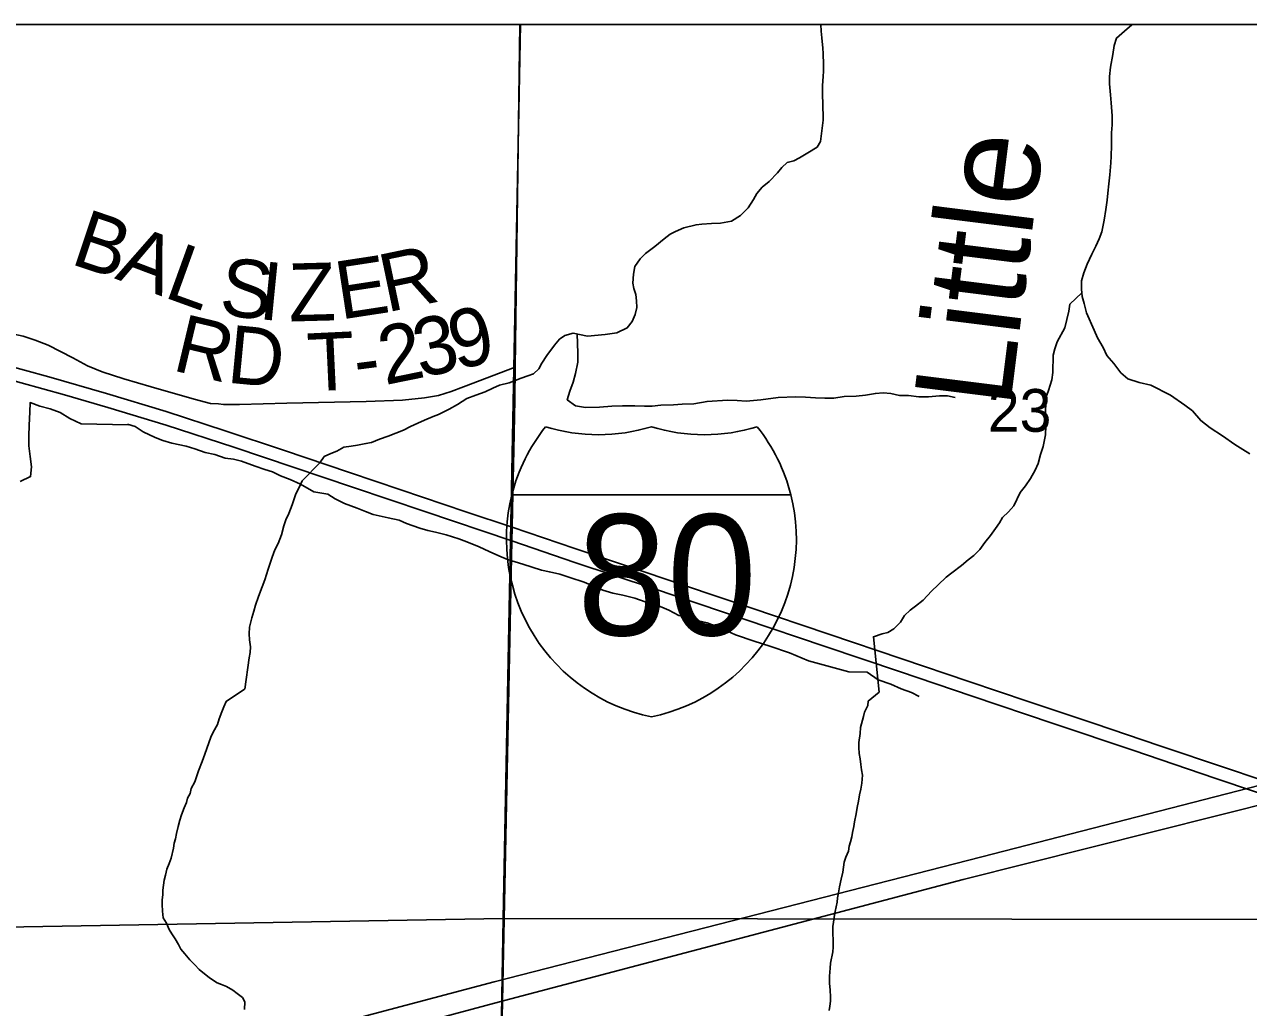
# Model space of a CAD drawing. Extents: x -8.5 to 18.7, y -20.3 to 7.
# Drawn here: x 6.749 to 9.147, y 5.013 to 6.938 of the extents above; entities that cross this region are included whole.
import ezdxf

# ---------------------------------------------------------------- set-up
doc = ezdxf.new("R2010")
doc.units = 0
for name, color, linetype in [('Default', 7, 'Continuous'), ('GM_X_Corporation', 7, 'Continuous'), ('GM_X_Interstate_Location', 7, 'Continuous'), ('GM_X_Interstate_Route', 7, 'Continuous'), ('GM_X_Interstate_Shield', 7, 'Continuous'), ('GM_X_Minor_River', 7, 'Continuous'), ('GM_X_Minor_River_Text', 7, 'Continuous'), ('GM_X_Rail_Line', 7, 'Continuous'), ('GM_X_Section', 7, 'Continuous'), ('GM_X_Section_Text', 7, 'Continuous'), ('GM_X_Township_Road', 7, 'Continuous'), ('GM_X_Township_Road_Text', 7, 'Continuous'), ('SH_Cut_Line', 7, 'Continuous')]:
    doc.layers.add(name, color=color, linetype=linetype)

msp = doc.modelspace()

# ---------------------------------------------------------------- linework, layer by layer
at = {"layer": 'Default'}
for points in [[(7.7208, 6.938), (5.7052, 6.938), (5.695, 5.1526), (7.6869, 5.1871)], [(9.7054, 6.938), (7.7208, 6.938), (7.6869, 5.1871), (9.6798, 5.1845)]]:
    msp.add_lwpolyline(points, close=True, dxfattribs=at)
at = {"layer": 'GM_X_Corporation'}
msp.add_lwpolyline([(3.6318, 1.1236), (5.043, 1.1473), (5.1251, 1.1484), (7.5383, 1.181), (7.59, 1.1818), (9.5569, 1.2131), (11.5871, 1.2389), (11.6132, 2.2462), (11.64, 3.2551), (11.6653, 4.2586), (11.6686, 4.5917), (11.6689, 4.6186), (11.6732, 5.0475), (11.7049, 6.938), (-0.1911, 6.938)], dxfattribs=at)
at = {"layer": 'GM_X_Interstate_Route'}
for points in [[(6.7004, 6.2739), (6.7966, 6.2478), (6.9096, 6.2154), (7.0268, 6.18), (7.1419, 6.1424), (7.2562, 6.1042), (7.3856, 6.0606), (7.4865, 6.0267), (7.6137, 5.9836), (7.7046, 5.9532), (7.8274, 5.9118), (7.9288, 5.8777), (8.0421, 5.839), (8.1703, 5.7961), (8.3249, 5.7439), (8.4679, 5.6957), (8.5992, 5.6514), (8.7155, 5.6122), (8.8446, 5.5689), (8.9735, 5.5253), (9.1021, 5.4821), (9.2338, 5.4376)], [(6.6997, 6.2477), (6.8274, 6.2128), (6.9123, 6.1881), (7.0264, 6.1533), (7.159, 6.1101), (7.3936, 6.0312), (7.5332, 5.9844), (7.7039, 5.9264), (7.8274, 5.8845), (7.9816, 5.8332), (8.1593, 5.7732), (8.3179, 5.7196), (8.4633, 5.6707), (8.6059, 5.6226), (8.7648, 5.5691), (8.9225, 5.5158), (9.0814, 5.4621), (9.2385, 5.4092)]]:
    msp.add_lwpolyline(points, dxfattribs=at)
at = {"layer": 'GM_X_Interstate_Shield'}
for p, q in [((7.704, 6.0169), (8.2505, 6.0169)), ((8.2505, 6.0169), (7.704, 6.0169)), ((8.2505, 6.0169), (7.704, 6.0169))]:
    msp.add_line(p, q, dxfattribs=at)
for centre, start, end in [((8.0483, 5.9299), 141.669, 165.8066), ((7.8735, 6.4897), 253.0091, 286.9909), ((8.081, 6.4897), 253.0091, 286.9909), ((7.9062, 5.9299), 14.1934, 38.331), ((8.0483, 5.9299), 165.8066, 258.463), ((7.9062, 5.9299), 281.537, 14.1934)]:
    msp.add_arc(centre, 0.3551, start, end, dxfattribs=at)
at = {"layer": 'GM_X_Minor_River'}
for points in [[(8.309, 6.938), (8.309, 6.938), (8.3098, 6.9251), (8.3114, 6.9121), (8.313, 6.8916), (8.3138, 6.881), (8.3147, 6.8597), (8.3147, 6.8468), (8.314, 6.8362), (8.3126, 6.8187), (8.3127, 6.7975), (8.3135, 6.7853), (8.3137, 6.7504), (8.3108, 6.7245), (8.3086, 6.7086), (8.3018, 6.6979), (8.2837, 6.6864), (8.2678, 6.6765), (8.2564, 6.6711), (8.2435, 6.668), (8.233, 6.6581), (8.2247, 6.6475), (8.208, 6.6307), (8.1944, 6.6192), (8.1839, 6.607), (8.1771, 6.5949), (8.1666, 6.5789), (8.1522, 6.5636), (8.134, 6.5529), (8.1128, 6.549), (8.0953, 6.5482), (8.0764, 6.5466), (8.065, 6.5458), (8.0407, 6.5396), (8.0248, 6.5327), (8.0142, 6.5274), (8.0021, 6.5182), (7.984, 6.5029), (7.9658, 6.4892), (7.9553, 6.4793), (7.9447, 6.464), (7.9425, 6.4488), (7.9411, 6.4314), (7.9426, 6.4207), (7.9465, 6.4094), (7.9481, 6.3965), (7.9489, 6.3835), (7.9452, 6.3699), (7.9399, 6.3562), (7.9301, 6.344), (7.9097, 6.334), (7.8869, 6.3309), (7.852, 6.3277), (7.8239, 6.3337), (7.808, 6.3291), (7.7974, 6.3214), (7.7876, 6.31), (7.7725, 6.2894), (7.7627, 6.2749), (7.7567, 6.2635), (7.7461, 6.2536), (7.7355, 6.2498), (7.7219, 6.2452), (7.6984, 6.236), (7.6794, 6.2313), (7.6666, 6.226), (7.6514, 6.2183), (7.6332, 6.2121), (7.6158, 6.2052), (7.5976, 6.1938), (7.581, 6.1846), (7.5605, 6.1739), (7.5499, 6.17), (7.5325, 6.1631), (7.5196, 6.157), (7.5052, 6.1509), (7.4916, 6.1432), (7.4764, 6.1378), (7.4613, 6.1317), (7.4446, 6.1256), (7.4287, 6.1194), (7.4181, 6.1171), (7.4014, 6.114), (7.3893, 6.1124)], [(8.9185, 6.938), (8.9186, 6.9373), (8.9042, 6.9251), (8.8883, 6.9114), (8.8839, 6.8969), (8.8817, 6.8795), (8.8765, 6.8544), (8.8751, 6.8361), (8.8751, 6.8217), (8.8768, 6.8004)], [(8.8768, 6.8004), (8.8784, 6.7845), (8.88, 6.7594), (8.8801, 6.7412), (8.8787, 6.726), (8.8788, 6.7009), (8.8781, 6.6804), (8.8774, 6.6668), (8.8753, 6.6432), (8.8738, 6.6257), (8.8717, 6.6075), (8.8702, 6.5938), (8.868, 6.5756), (8.8643, 6.555), (8.8599, 6.5322), (8.8547, 6.5185), (8.8479, 6.5041), (8.8404, 6.4881), (8.8314, 6.4683), (8.8246, 6.4516), (8.8202, 6.4356), (8.8202, 6.4197), (8.8211, 6.4052), (8.8249, 6.3916), (8.8296, 6.3734), (8.8449, 6.3392), (8.8511, 6.3241), (8.8626, 6.3051), (8.8695, 6.29), (8.8832, 6.2741), (8.897, 6.2559), (8.9107, 6.2438), (8.9328, 6.237), (8.9556, 6.2318), (8.9944, 6.2122), (9.0226, 6.1926), (9.0378, 6.1812), (9.0538, 6.1623), (9.0721, 6.148), (9.0965, 6.1321), (9.1201, 6.1155), (9.1361, 6.1057), (9.1498, 6.0974)], [(8.8207, 6.4124), (8.7969, 6.3899), (8.7954, 6.3763), (8.7872, 6.3436), (8.7722, 6.3162), (8.7677, 6.3025), (8.7647, 6.2903), (8.7641, 6.2561), (8.7619, 6.2417), (8.7552, 6.2211), (8.7507, 6.209), (8.75, 6.1968), (8.7493, 6.1793), (8.7502, 6.1664), (8.7502, 6.152), (8.7496, 6.1345), (8.7451, 6.1117), (8.7399, 6.0957), (8.7354, 6.0783), (8.7294, 6.0653), (8.7204, 6.0486), (8.7106, 6.0341), (8.7, 6.0211), (8.6873, 5.9953), (8.6767, 5.9838), (8.6654, 5.9724), (8.6593, 5.9617), (8.6518, 5.9511), (8.642, 5.9374), (8.6307, 5.9236), (8.6209, 5.9099), (8.6088, 5.8977), (8.5982, 5.8893), (8.5846, 5.8786), (8.5657, 5.8641), (8.5551, 5.8557), (8.5393, 5.8405), (8.5264, 5.8283), (8.5098, 5.8107), (8.4947, 5.7985), (8.4841, 5.7909), (8.4735, 5.7802), (8.4652, 5.7673), (8.4524, 5.7543), (8.4403, 5.7474), (8.4297, 5.7443), (8.4122, 5.739), (8.4234, 5.63)], [(7.8318, 6.332), (7.8331, 6.2944), (7.8334, 6.2769), (7.8289, 6.2542), (7.8239, 6.2377), (7.8173, 6.2196), (7.8123, 6.203), (7.8287, 6.1912), (7.8483, 6.1876), (7.8757, 6.1883), (7.9, 6.1906), (7.9205, 6.1908), (7.9448, 6.1909), (7.9638, 6.1903), (7.979, 6.1906), (7.9958, 6.1924), (8.0208, 6.1932), (8.0376, 6.1943), (8.0604, 6.1951), (8.0863, 6.1997), (8.1266, 6.2023), (8.1456, 6.2018), (8.163, 6.2005), (8.192, 6.2027), (8.2255, 6.2071), (8.2605, 6.2084), (8.2794, 6.2078), (8.2991, 6.2065), (8.3174, 6.206), (8.3348, 6.2062), (8.3547, 6.2094), (8.3782, 6.2103), (8.3965, 6.212), (8.4163, 6.2153), (8.4316, 6.2163), (8.4467, 6.2152), (8.4633, 6.2116), (8.4808, 6.2111), (8.5012, 6.209), (8.5202, 6.2085), (8.5415, 6.2109), (8.5574, 6.2104), (8.5726, 6.2077)], [(6.7406, 6.0427), (6.7611, 6.0524), (6.7628, 6.0714), (6.7599, 6.0919), (6.7578, 6.1125), (6.7572, 6.1315), (6.7581, 6.1535), (6.7598, 6.1786), (6.7599, 6.1976), (6.7788, 6.1906), (6.7993, 6.1851), (6.819, 6.1781), (6.8378, 6.1665), (6.8598, 6.1557), (6.9522, 6.1538)], [(6.9506, 6.1549), (6.9656, 6.1507), (6.9813, 6.1404), (7.0053, 6.129), (7.0203, 6.1233), (7.0376, 6.1182), (7.0655, 6.1121), (7.0828, 6.1071), (7.1031, 6.0996), (7.122, 6.096), (7.1423, 6.0886), (7.1582, 6.0866), (7.174, 6.0824), (7.2011, 6.0732), (7.2199, 6.0666), (7.2349, 6.0616), (7.2507, 6.0543), (7.2695, 6.047), (7.2897, 6.038), (7.3159, 6.0228), (7.3431, 6.0182), (7.358, 6.0087), (7.3759, 5.9998), (7.4007, 5.9907), (7.4173, 5.9842), (7.4323, 5.9784), (7.4617, 5.9715), (7.4828, 5.9671), (7.4978, 5.9606), (7.5234, 5.9515), (7.5392, 5.9472), (7.5543, 5.9438), (7.5754, 5.9386), (7.6003, 5.9303), (7.616, 5.9245), (7.6401, 5.9147), (7.6595, 5.9058), (7.6783, 5.8976), (7.6956, 5.8903), (7.7257, 5.8811), (7.7618, 5.8694), (7.7776, 5.8659), (7.798, 5.8615), (7.8176, 5.8549), (7.8454, 5.8457), (7.8627, 5.8384), (7.8822, 5.8302), (7.9017, 5.8243), (7.9214, 5.82), (7.9448, 5.8147), (7.965, 5.8073), (7.9854, 5.8022), (8.0117, 5.7908), (8.0311, 5.7803), (8.0522, 5.7759), (8.0695, 5.7701), (8.0869, 5.7658), (8.1087, 5.7576), (8.1252, 5.7503), (8.1424, 5.7429), (8.1785, 5.7305), (8.2094, 5.7205), (8.2477, 5.7072), (8.2852, 5.6917), (8.3644, 5.6704), (8.4, 5.6694), (8.4216, 5.6543), (8.4464, 5.646), (8.4667, 5.6371), (8.487, 5.6296), (8.5019, 5.6216)], [(7.3893, 6.1124), (7.3749, 6.1101), (7.3612, 6.1024), (7.3491, 6.0978), (7.3362, 6.0917), (7.3279, 6.0795), (7.2932, 6.0444), (7.2864, 6.03), (7.2804, 6.0186), (7.2737, 5.9973), (7.267, 5.9805), (7.261, 5.9676), (7.2572, 5.9562), (7.2528, 5.9387), (7.246, 5.9212), (7.2392, 5.909), (7.234, 5.8946), (7.2265, 5.871), (7.2198, 5.8505), (7.2146, 5.8368), (7.2078, 5.8177), (7.2018, 5.801), (7.1981, 5.7888), (7.1944, 5.7759), (7.1899, 5.7577), (7.1892, 5.7447), (7.19, 5.7326), (7.1916, 5.7189), (7.1909, 5.7083), (7.1895, 5.6977), (7.1805, 5.6359)], [(7.1799, 5.6359), (7.1442, 5.6123), (7.1397, 5.6017), (7.1359, 5.5918), (7.1307, 5.5781), (7.1269, 5.5667), (7.1187, 5.5522), (7.1142, 5.5423), (7.1022, 5.5088), (7.0969, 5.4943), (7.0902, 5.4761), (7.0865, 5.4662), (7.0827, 5.4548), (7.0759, 5.4418), (7.0737, 5.4319), (7.0685, 5.4228), (7.0662, 5.4144), (7.0617, 5.4038), (7.0565, 5.3901), (7.0535, 5.3794), (7.0498, 5.3672), (7.0468, 5.3535), (7.0446, 5.3429), (7.0423, 5.3345), (7.0409, 5.3246), (7.0364, 5.3049), (7.0327, 5.295), (7.0282, 5.2836), (7.0252, 5.2721), (7.0229, 5.2623), (7.02, 5.2425), (7.0201, 5.2341), (7.0186, 5.2227), (7.0186, 5.2144), (7.0195, 5.2015), (7.021, 5.1886), (7.0272, 5.1779), (7.0325, 5.1658), (7.0379, 5.1567), (7.044, 5.1469), (7.0509, 5.1363), (7.0555, 5.1272), (7.0632, 5.1181), (7.0731, 5.106), (7.083, 5.0962), (7.0914, 5.0871), (7.1112, 5.0705), (7.1265, 5.0607), (7.1348, 5.0577), (7.1447, 5.0539), (7.1569, 5.0464), (7.166, 5.0403), (7.176, 5.032), (7.1806, 5.0237), (7.1799, 5.0085)], [(8.4234, 5.63), (8.4022, 5.613), (8.4015, 5.6039), (8.3947, 5.591), (8.3932, 5.5826), (8.3873, 5.5613), (8.3866, 5.5491), (8.3836, 5.5316), (8.3837, 5.5218), (8.3845, 5.5104), (8.3861, 5.4997), (8.3876, 5.4884), (8.3892, 5.4785), (8.3908, 5.4679), (8.3893, 5.4519), (8.3879, 5.4405), (8.3849, 5.4291), (8.3834, 5.4169), (8.3805, 5.4047), (8.3783, 5.3918), (8.3753, 5.3766), (8.3738, 5.3675), (8.3716, 5.3553), (8.3701, 5.347), (8.3671, 5.3371), (8.3649, 5.3287), (8.3634, 5.3188), (8.3582, 5.3074), (8.3552, 5.2975), (8.3537, 5.2876), (8.3523, 5.2777), (8.3493, 5.264), (8.3456, 5.2488), (8.3441, 5.2374), (8.3419, 5.2275), (8.3412, 5.2192), (8.3375, 5.2009), (8.3352, 5.1895), (8.3338, 5.1796), (8.3331, 5.1713), (8.3333, 5.131), (8.3325, 5.1219), (8.3281, 5.0998), (8.3274, 5.09), (8.326, 5.074), (8.326, 5.0603), (8.3276, 5.0466), (8.3284, 5.0337), (8.3285, 5.0254), (8.327, 5.0155), (8.3255, 5.0071)]]:
    msp.add_lwpolyline(points, dxfattribs=at)
at = {"layer": 'GM_X_Rail_Line'}
for points in [[(3.3492, 3.6263), (4.4113, 3.9753), (4.8681, 4.1485), (5.3383, 4.3406), (5.8491, 4.5056), (6.1923, 4.6193), (6.6809, 4.7548), (6.9366, 4.825), (7.6892, 5.0264), (8.5879, 5.2635), (9.4613, 5.4827), (11.0096, 5.9016), (11.7084, 6.0715), (12.7137, 6.343), (13.3579, 6.5187), (14.1524, 6.7238), (14.6912, 6.8722), (14.936, 6.938)], [(3.8129, 4.1403), (4.3242, 4.207), (4.4317, 4.2229), (4.6591, 4.2738), (5.1343, 4.3961), (5.6672, 4.5409), (6.9377, 4.8691), (7.6692, 5.0633), (8.6247, 5.3078), (9.4518, 5.5207), (10.9979, 5.9173), (11.7143, 6.0969), (12.7059, 6.3644), (13.315, 6.5285), (14.1271, 6.7413), (14.6717, 6.8937), (14.8429, 6.938)]]:
    msp.add_lwpolyline(points, dxfattribs=at)
at = {"layer": 'GM_X_Section'}
for points in [[(7.6869, 5.1871), (7.6532, 3.1997), (5.6525, 3.1789), (5.695, 5.1526)], [(9.6798, 5.1845), (9.6423, 3.2228), (7.6532, 3.1997), (7.6869, 5.1871)]]:
    msp.add_lwpolyline(points, close=True, dxfattribs=at)
at = {"layer": 'GM_X_Township_Road'}
msp.add_line((7.7104, 6.2666), (7.7196, 6.938), dxfattribs=at)
for points in [[(6.7013, 6.3356), (6.7191, 6.3335), (6.7463, 6.3274), (6.77, 6.3198), (6.7952, 6.3101), (6.8435, 6.2852), (6.8724, 6.2696), (6.9015, 6.2575), (6.9435, 6.2439), (6.9973, 6.2284), (7.0815, 6.2044), (7.1133, 6.1958), (7.1291, 6.1947)], [(7.1291, 6.1947), (7.139, 6.194), (7.1705, 6.194), (7.2632, 6.1965), (7.4182, 6.1993), (7.4897, 6.2025), (7.5329, 6.2069), (7.5603, 6.2111), (7.5853, 6.2191), (7.6094, 6.2286), (7.7104, 6.2666)], [(7.6765, 4.5738), (7.7039, 5.9264), (7.7046, 5.9532), (7.7061, 6.0185), (7.7076, 6.104), (7.7095, 6.2035), (7.7104, 6.2666)]]:
    msp.add_lwpolyline(points, dxfattribs=at)
at = {"layer": 'SH_Cut_Line'}
msp.add_lwpolyline([(18.7413, -10.9039), (18.7413, 6.938), (-8.4587, 6.938)], dxfattribs=at)

# ---------------------------------------------------------------- texts
at = {"layer": 'GM_X_Interstate_Location'}
for s in ['-', '.', ',']:
    msp.add_text(s, height=0.000379, dxfattribs=at).set_placement((7.9772, 5.8658))
msp.add_text('80', height=0.000379, rotation=0, dxfattribs=at).set_placement((7.8998, 5.7874))
at = {"layer": 'GM_X_Interstate_Shield'}
msp.add_text('80', height=0.23674, dxfattribs=at).set_placement((7.8318, 5.7417))
at = {"layer": 'GM_X_Minor_River_Text'}
msp.add_text('Little', height=0.18951, rotation=82.8561, dxfattribs=at).set_placement((8.6795, 6.1838))
at = {"layer": 'GM_X_Section_Text'}
msp.add_text('23', height=0.08371, rotation=0, dxfattribs=at).set_placement((8.6365, 6.1403))
at = {"layer": 'GM_X_Township_Road_Text'}
for s, rotation, p in [('B', 341.5367, (6.8367, 6.47)), ('A', 339.3101, (6.9242, 6.4409)), ('L', 340.1392, (7.0194, 6.4049)), ('R', 11.8292, (7.4586, 6.3738)), ('S', 354.0647, (7.1287, 6.3693)), ('E', 8.6974, (7.3679, 6.3598)), ('I', 354.3169, (7.2055, 6.3613)), ('Z', 1.5316, (7.2675, 6.3561)), ('9', 13.4153, (7.5951, 6.2608)), ('R', 346.5601, (7.036, 6.2613)), ('2', 11.4916, (7.4551, 6.2315)), ('3', 12.0447, (7.5243, 6.2456)), ('D', 354.5113, (7.1435, 6.2368)), ('T', 2.7223, (7.3057, 6.2192)), ('-', 7.3565, (7.4004, 6.2241))]:
    msp.add_text(s, height=0.1136, rotation=rotation, dxfattribs=at).set_placement(p)

doc.saveas('drawing.dxf')
